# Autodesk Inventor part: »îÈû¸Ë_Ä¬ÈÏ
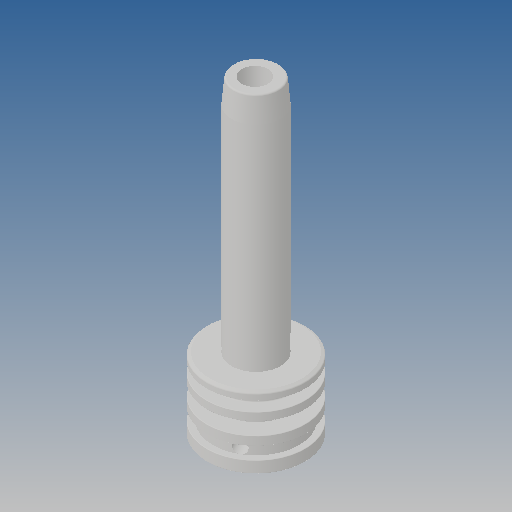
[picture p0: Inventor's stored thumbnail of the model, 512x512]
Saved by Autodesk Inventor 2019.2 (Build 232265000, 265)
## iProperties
Created: 2011-12
Part Number: »îÈû¸Ë_Ä¬ÈÏ
Material: Ogólny
Document SubType Name: Modeling
Designer: CADENGINEERING4
Density: 1 g/cm^3
Appearance: Domyślna
Author: CADENGINEERING4
Revision Number: ÈÎºÎ
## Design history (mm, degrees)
feature "NONE"
node "Bryła1"
